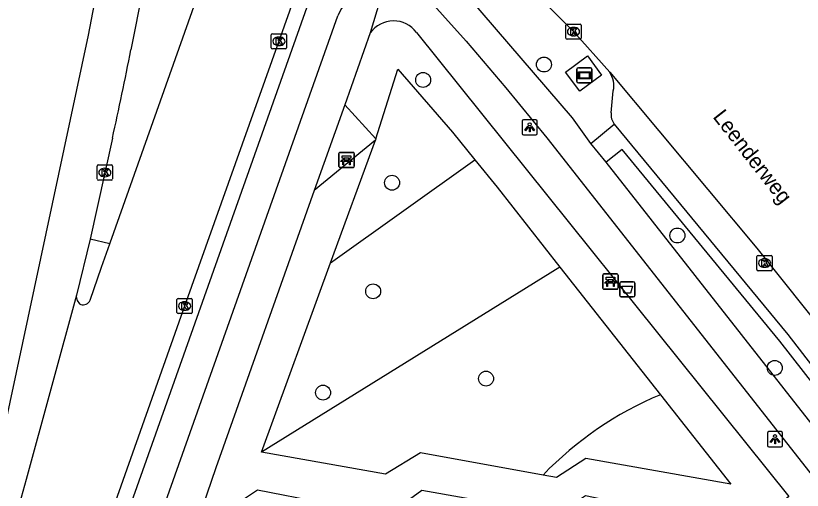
# Model space of a CAD drawing. Extents: x 161845 to 162341, y 381620 to 382158.
# Drawn here: x 161927.1 to 161978.7, y 382079 to 382110.2 of the extents above; entities that cross this region are included whole.
import ezdxf

# ---------------------------------------------------------------- set-up
doc = ezdxf.new("R2010")
doc.units = 0
for name, color, linetype in [('IMGEO_Afvalbak', 7, 'Continuous'), ('IMGEO_Bank', 7, 'Continuous'), ('IMGEO_Boom', 7, 'Continuous'), ('IMGEO_Fietspad_gesloten', 7, 'Continuous'), ('IMGEO_Groenvoorziening', 7, 'Continuous'), ('IMGEO_Kolk', 7, 'Continuous'), ('IMGEO_Lichtpunt', 7, 'Continuous'), ('IMGEO_Openbare_ruimte_label', 7, 'Continuous'), ('IMGEO_OVBaan_gesloten', 7, 'Continuous'), ('IMGEO_Parkeervlak_open', 7, 'Continuous'), ('IMGEO_Reclamebord', 7, 'Continuous'), ('IMGEO_Rijbaan_lokaal_gesloten', 7, 'Continuous'), ('IMGEO_Verkeerseiland_groen', 7, 'Continuous'), ('IMGEO_Voetpad_open', 7, 'Continuous')]:
    doc.layers.add(name, color=color, linetype=linetype)

msp = doc.modelspace()

# ---------------------------------------------------------------- linework, layer by layer
at = {"layer": 'IMGEO_Afvalbak'}
for p, q in [((161966.754, 382091.842), (161966.754, 382092.642)), ((161966.754, 382092.642), (161966.754, 382091.842)), ((161966.854, 382092.742), (161967.644, 382092.742)), ((161967.644, 382092.742), (161966.854, 382092.742)), ((161967.744, 382092.642), (161967.744, 382091.842)), ((161967.744, 382091.842), (161967.744, 382092.642)), ((161967.644, 382091.742), (161966.854, 382091.742)), ((161966.854, 382091.742), (161967.644, 382091.742))]:
    msp.add_line(p, q, dxfattribs=at)
msp.add_lwpolyline([(161966.897, 382092.456), (161967.601, 382092.456), (161967.452, 382091.986), (161967.046, 382091.986), (161966.897, 382092.456)], dxfattribs=at)
for centre, start, end in [((161966.854, 382092.642), 90, 180), ((161966.854, 382092.642), 90, 180), ((161967.644, 382092.642), 0, 90), ((161967.644, 382092.642), 360, 90), ((161966.854, 382091.842), 180, 270), ((161966.854, 382091.842), 180, 270), ((161967.644, 382091.842), 270, 0), ((161967.644, 382091.842), 270, 0)]:
    msp.add_arc(centre, 0.1, start, end, dxfattribs=at)
at = {"layer": 'IMGEO_Bank'}
for p, q in [((161948.316, 382100.316), (161948.316, 382101.157)), ((161948.316, 382101.157), (161948.316, 382100.316)), ((161948.391, 382101.241), (161949.232, 382101.241)), ((161949.232, 382101.241), (161948.391, 382101.241)), ((161949.316, 382101.166), (161949.316, 382100.325)), ((161949.316, 382100.325), (161949.316, 382101.166)), ((161949.013, 382100.639), (161948.62, 382100.639)), ((161948.625, 382100.747), (161948.625, 382100.853)), ((161948.669, 382100.853), (161948.669, 382100.747)), ((161948.957, 382100.859), (161948.675, 382100.859)), ((161948.675, 382100.741), (161948.957, 382100.741)), ((161948.963, 382100.747), (161948.963, 382100.853)), ((161949.007, 382100.853), (161949.007, 382100.747)), ((161949.241, 382100.241), (161948.4, 382100.241)), ((161948.4, 382100.241), (161949.241, 382100.241)), ((161965.645, 382092.331), (161965.645, 382093.172)), ((161965.645, 382093.172), (161965.645, 382092.331)), ((161965.72, 382093.256), (161966.561, 382093.256)), ((161966.561, 382093.256), (161965.72, 382093.256)), ((161966.286, 382092.874), (161966.004, 382092.874)), ((161966.645, 382093.181), (161966.645, 382092.34)), ((161966.645, 382092.34), (161966.645, 382093.181)), ((161966.342, 382092.654), (161965.949, 382092.654)), ((161965.954, 382092.762), (161965.954, 382092.868)), ((161965.998, 382092.868), (161965.998, 382092.762)), ((161966.004, 382092.756), (161966.286, 382092.756)), ((161966.292, 382092.762), (161966.292, 382092.868)), ((161966.336, 382092.868), (161966.336, 382092.762)), ((161966.57, 382092.256), (161965.729, 382092.256)), ((161965.729, 382092.256), (161966.57, 382092.256))]:
    msp.add_line(p, q, dxfattribs=at)
for points in [[(161948.563, 382100.639), (161948.421, 382100.639), (161948.533, 382100.741), (161948.619, 382100.741)], [(161948.619, 382100.859), (161948.533, 382100.859), (161948.533, 382101.02), (161949.096, 382101.02), (161949.096, 382100.859), (161949.013, 382100.859)], [(161948.613, 382100.632), (161948.613, 382100.425), (161948.57, 382100.425), (161948.57, 382100.632)], [(161949.013, 382100.741), (161949.096, 382100.741), (161949.208, 382100.639), (161949.069, 382100.639)], [(161949.063, 382100.632), (161949.063, 382100.425), (161949.019, 382100.425), (161949.019, 382100.632)], [(161965.948, 382092.874), (161965.862, 382092.874), (161965.862, 382093.035), (161966.425, 382093.035), (161966.425, 382092.874), (161966.342, 382092.874)], [(161965.892, 382092.654), (161965.75, 382092.654), (161965.862, 382092.756), (161965.948, 382092.756)], [(161965.942, 382092.647), (161965.942, 382092.44), (161965.899, 382092.44), (161965.899, 382092.647)], [(161966.342, 382092.756), (161966.425, 382092.756), (161966.537, 382092.654), (161966.398, 382092.654)], [(161966.392, 382092.647), (161966.392, 382092.44), (161966.348, 382092.44), (161966.348, 382092.647)]]:
    msp.add_lwpolyline(points, dxfattribs=at)
for centre, radius, start, end in [((161948.394, 382101.163), 0.0779, 92.4484, 184.2845), ((161948.394, 382101.163), 0.0779, 92.4484, 184.2845), ((161949.238, 382101.163), 0.0779, 2.4484, 94.2845), ((161949.238, 382101.163), 0.0779, 2.4484, 94.2845), ((161948.563, 382100.632), 0.00671, 2.8957, 87.1043), ((161948.62, 382100.632), 0.00671, 92.8957, 177.1043), ((161948.618, 382100.852), 0.00671, 2.8957, 87.1043), ((161948.618, 382100.748), 0.00671, 272.8957, 357.1043), ((161948.675, 382100.852), 0.00671, 92.8957, 177.1043), ((161948.675, 382100.748), 0.00671, 182.8957, 267.1043), ((161948.957, 382100.852), 0.00671, 2.8957, 87.1043), ((161948.957, 382100.748), 0.00671, 272.8957, 357.1043), ((161949.014, 382100.852), 0.00671, 92.8957, 177.1043), ((161949.014, 382100.748), 0.00671, 182.8957, 267.1043), ((161949.012, 382100.632), 0.00671, 2.8957, 87.1043), ((161949.069, 382100.632), 0.00671, 92.8957, 177.1043), ((161948.394, 382100.319), 0.0779, 182.4484, 274.2845), ((161948.394, 382100.319), 0.0779, 182.4484, 274.2845), ((161949.238, 382100.319), 0.0779, 272.4484, 4.2845), ((161949.238, 382100.319), 0.0779, 272.4484, 4.2845), ((161965.723, 382093.178), 0.0779, 92.4484, 184.2845), ((161965.723, 382093.178), 0.0779, 92.4484, 184.2845), ((161965.947, 382092.867), 0.00671, 2.8957, 87.1043), ((161966.004, 382092.867), 0.00671, 92.8957, 177.1043), ((161966.286, 382092.867), 0.00671, 2.8957, 87.1043), ((161966.343, 382092.867), 0.00671, 92.8957, 177.1043), ((161966.567, 382093.178), 0.0779, 2.4484, 94.2845), ((161966.567, 382093.178), 0.0779, 2.4484, 94.2845), ((161965.892, 382092.647), 0.00671, 2.8957, 87.1043), ((161965.949, 382092.647), 0.00671, 92.8957, 177.1043), ((161965.947, 382092.763), 0.00671, 272.8957, 357.1043), ((161966.004, 382092.763), 0.00671, 182.8957, 267.1043), ((161966.286, 382092.763), 0.00671, 272.8957, 357.1043), ((161966.343, 382092.763), 0.00671, 182.8957, 267.1043), ((161966.341, 382092.647), 0.00671, 2.8957, 87.1043), ((161966.398, 382092.647), 0.00671, 92.8957, 177.1043), ((161965.723, 382092.334), 0.0779, 182.4484, 274.2845), ((161965.723, 382092.334), 0.0779, 182.4484, 274.2845), ((161966.567, 382092.334), 0.0779, 272.4484, 4.2845), ((161966.567, 382092.334), 0.0779, 272.4484, 4.2845)]:
    msp.add_arc(centre, radius, start, end, dxfattribs=at)
at = {"layer": 'IMGEO_Boom'}
for centre in [(161961.778, 382107.01), (161953.848, 382106), (161951.807, 382099.243), (161970.541, 382095.78), (161950.565, 382092.113), (161976.936, 382087.084), (161957.978, 382086.381), (161947.278, 382085.46)]:
    msp.add_circle(centre, 0.489, dxfattribs=at)
at = {"layer": 'IMGEO_Fietspad_gesloten'}
for points in [[(161929.692, 382064.104), (161946.705, 382112.189)], [(161930.559, 382060.292), (161948.248, 382110.215)]]:
    msp.add_lwpolyline(points, dxfattribs=at)
msp.add_arc((161951.718, 382108.75), 3.767, 94.7236, 157.1131, dxfattribs=at)
at = {"layer": 'IMGEO_Groenvoorziening'}
for points in [[(161950.738, 382102.124), (161952.187, 382106.704), (161955.767, 382102.569), (161957.25, 382100.745)], [(161947.765, 382093.975), (161950.71, 382102.036)], [(161947.765, 382093.975), (161957.25, 382100.745)], [(161957.25, 382100.745), (161958.711, 382098.948), (161962.832, 382093.707)], [(161943.229, 382081.558), (161947.765, 382093.975)], [(161962.832, 382093.707), (161943.229, 382081.558)], [(161962.832, 382093.707), (161969.423, 382085.325)], [(161969.423, 382085.325), (161974.048, 382079.443), (161964.538, 382081.14), (161962.599, 382079.888), (161961.719, 382080.048)], [(161961.719, 382080.048), (161953.667, 382081.508), (161951.366, 382080.101), (161943.229, 382081.558)]]:
    msp.add_lwpolyline(points, dxfattribs=at)
msp.add_arc((161978.375, 382063.993), 23.134, 112.7665, 136.0534, dxfattribs=at)
at = {"layer": 'IMGEO_Kolk'}
for p, q in [((161963.221, 382108.744), (161963.221, 382109.596)), ((161963.296, 382109.67), (161964.148, 382109.67)), ((161963.709, 382109.45), (161963.734, 382109.45)), ((161964.222, 382109.596), (161964.222, 382108.744)), ((161943.879, 382108.109), (161943.879, 382108.961)), ((161943.954, 382109.035), (161944.806, 382109.035)), ((161944.88, 382108.961), (161944.88, 382108.109)), ((161963.732, 382108.89), (161963.707, 382108.89)), ((161944.367, 382108.815), (161944.392, 382108.815)), ((161964.148, 382108.67), (161963.296, 382108.67)), ((161944.806, 382108.035), (161943.954, 382108.035)), ((161944.39, 382108.255), (161944.365, 382108.255)), ((161932.448, 382099.491), (161932.448, 382100.343)), ((161932.523, 382100.417), (161933.375, 382100.417)), ((161932.936, 382100.197), (161932.961, 382100.197)), ((161933.449, 382100.343), (161933.449, 382099.491)), ((161932.959, 382099.637), (161932.934, 382099.637)), ((161933.375, 382099.417), (161932.523, 382099.417)), ((161975.841, 382094.469), (161976.693, 382094.469)), ((161975.766, 382093.543), (161975.766, 382094.395)), ((161976.254, 382094.249), (161976.279, 382094.249)), ((161976.767, 382094.395), (161976.767, 382093.543)), ((161976.693, 382093.469), (161975.841, 382093.469)), ((161976.277, 382093.689), (161976.252, 382093.689)), ((161937.686, 382090.721), (161937.686, 382091.573)), ((161937.761, 382091.647), (161938.613, 382091.647)), ((161938.174, 382091.427), (161938.199, 382091.427)), ((161938.687, 382091.573), (161938.687, 382090.721)), ((161938.197, 382090.867), (161938.172, 382090.867)), ((161938.613, 382090.647), (161937.761, 382090.647))]:
    msp.add_line(p, q, dxfattribs=at)
for points in [[(161963.221, 382108.744), (161963.221, 382109.596)], [(161963.296, 382109.67), (161964.148, 382109.67)], [(161964.222, 382109.596), (161964.222, 382108.744)], [(161943.879, 382108.109), (161943.879, 382108.961)], [(161943.954, 382109.035), (161944.806, 382109.035)], [(161944.88, 382108.961), (161944.88, 382108.109)], [(161963.542, 382109.37), (161963.665, 382109.37), (161963.665, 382109.219), (161963.795, 382109.37), (161963.959, 382109.37), (161963.813, 382109.219), (161963.966, 382108.97), (161963.814, 382108.97), (161963.729, 382109.134), (161963.665, 382109.067), (161963.665, 382108.97), (161963.542, 382108.97), (161963.542, 382109.37)], [(161944.2, 382108.735), (161944.323, 382108.735), (161944.323, 382108.584), (161944.453, 382108.735), (161944.617, 382108.735), (161944.471, 382108.584), (161944.624, 382108.335), (161944.472, 382108.335), (161944.387, 382108.499), (161944.323, 382108.432), (161944.323, 382108.335), (161944.2, 382108.335), (161944.2, 382108.735)], [(161964.148, 382108.67), (161963.296, 382108.67)], [(161944.806, 382108.035), (161943.954, 382108.035)], [(161932.448, 382099.491), (161932.448, 382100.343)], [(161932.523, 382100.417), (161933.375, 382100.417)], [(161932.769, 382100.117), (161932.892, 382100.117), (161932.892, 382099.966), (161933.022, 382100.117), (161933.186, 382100.117), (161933.04, 382099.966), (161933.193, 382099.717), (161933.041, 382099.717), (161932.956, 382099.881), (161932.892, 382099.814), (161932.892, 382099.717), (161932.769, 382099.717), (161932.769, 382100.117)], [(161933.449, 382100.343), (161933.449, 382099.491)], [(161933.375, 382099.417), (161932.523, 382099.417)], [(161975.841, 382094.469), (161976.693, 382094.469)], [(161975.766, 382093.543), (161975.766, 382094.395)], [(161976.087, 382094.169), (161976.21, 382094.169), (161976.21, 382094.018), (161976.34, 382094.169), (161976.504, 382094.169), (161976.358, 382094.018), (161976.511, 382093.769), (161976.359, 382093.769), (161976.274, 382093.933), (161976.21, 382093.866), (161976.21, 382093.769), (161976.087, 382093.769), (161976.087, 382094.169)], [(161976.767, 382094.395), (161976.767, 382093.543)], [(161976.693, 382093.469), (161975.841, 382093.469)], [(161937.686, 382090.721), (161937.686, 382091.573)], [(161937.761, 382091.647), (161938.613, 382091.647)], [(161938.007, 382091.347), (161938.13, 382091.347), (161938.13, 382091.196), (161938.26, 382091.347), (161938.424, 382091.347), (161938.278, 382091.196), (161938.431, 382090.947), (161938.279, 382090.947), (161938.194, 382091.111), (161938.13, 382091.044), (161938.13, 382090.947), (161938.007, 382090.947), (161938.007, 382091.347)], [(161938.687, 382091.573), (161938.687, 382090.721)], [(161938.613, 382090.647), (161937.761, 382090.647)]]:
    msp.add_lwpolyline(points, dxfattribs=at)
for centre, start, end in [((161963.298, 382109.594), 91.552, 178.448), ((161963.298, 382109.594), 91.552, 178.448), ((161964.146, 382109.594), 1.552, 88.448), ((161964.146, 382109.594), 1.552, 88.448), ((161943.956, 382108.959), 91.552, 178.448), ((161943.956, 382108.959), 91.552, 178.448), ((161944.804, 382108.959), 1.552, 88.448), ((161944.804, 382108.959), 1.552, 88.448), ((161963.298, 382108.746), 181.552, 268.448), ((161963.298, 382108.746), 181.552, 268.448), ((161964.146, 382108.746), 271.552, 358.448), ((161964.146, 382108.746), 271.552, 358.448), ((161943.956, 382108.111), 181.552, 268.448), ((161943.956, 382108.111), 181.552, 268.448), ((161944.804, 382108.111), 271.552, 358.448), ((161944.804, 382108.111), 271.552, 358.448), ((161932.525, 382100.341), 91.552, 178.448), ((161932.525, 382100.341), 91.552, 178.448), ((161933.373, 382100.341), 1.552, 88.448), ((161933.373, 382100.341), 1.552, 88.448), ((161932.525, 382099.493), 181.552, 268.448), ((161932.525, 382099.493), 181.552, 268.448), ((161933.373, 382099.493), 271.552, 358.448), ((161933.373, 382099.493), 271.552, 358.448), ((161975.843, 382094.393), 91.552, 178.448), ((161975.843, 382094.393), 91.552, 178.448), ((161976.691, 382094.393), 1.552, 88.448), ((161976.691, 382094.393), 1.552, 88.448), ((161975.843, 382093.545), 181.552, 268.448), ((161975.843, 382093.545), 181.552, 268.448), ((161976.691, 382093.545), 271.552, 358.448), ((161976.691, 382093.545), 271.552, 358.448), ((161937.763, 382091.571), 91.552, 178.448), ((161937.763, 382091.571), 91.552, 178.448), ((161938.611, 382091.571), 1.552, 88.448), ((161938.611, 382091.571), 1.552, 88.448), ((161937.763, 382090.723), 181.552, 268.448), ((161937.763, 382090.723), 181.552, 268.448), ((161938.611, 382090.723), 271.552, 358.448), ((161938.611, 382090.723), 271.552, 358.448)]:
    msp.add_arc(centre, 0.0765, start, end, dxfattribs=at)
for centre, major_axis, ratio, start_param, end_param in [((161963.708, 382109.17), (-0.387, 0.002), 0.722429, 4.712389, 7.853982), ((161963.733, 382109.17), (-0.39, 0.002), 0.717154, 1.570796, 4.712389), ((161944.366, 382108.535), (-0.387, 0.002), 0.722429, 4.712389, 7.853982), ((161944.391, 382108.535), (-0.39, 0.002), 0.717154, 1.570796, 4.712389), ((161932.935, 382099.917), (-0.387, 0.002), 0.722429, 4.712389, 7.853982), ((161932.96, 382099.917), (-0.39, 0.002), 0.717154, 1.570796, 4.712389), ((161976.253, 382093.969), (-0.387, 0.002), 0.722429, 4.712389, 7.853982), ((161976.278, 382093.969), (-0.39, 0.002), 0.717154, 1.570796, 4.712389), ((161938.173, 382091.147), (-0.387, 0.002), 0.722429, 4.712389, 7.853982), ((161938.198, 382091.147), (-0.39, 0.002), 0.717154, 1.570796, 4.712389)]:
    msp.add_ellipse(centre, major_axis=major_axis, ratio=ratio, start_param=start_param, end_param=end_param, dxfattribs=at)
at = {"layer": 'IMGEO_Lichtpunt'}
for p, q in [((161960.347, 382103.288), (161960.347, 382102.481)), ((161960.347, 382103.288), (161960.347, 382102.481)), ((161961.249, 382103.383), (161960.441, 382103.383)), ((161961.249, 382103.383), (161960.441, 382103.383)), ((161961.343, 382102.481), (161961.343, 382103.288)), ((161961.343, 382102.481), (161961.343, 382103.288)), ((161960.441, 382102.387), (161961.249, 382102.387)), ((161960.441, 382102.387), (161961.249, 382102.387)), ((161976.454, 382082.803), (161976.454, 382081.996)), ((161976.454, 382082.803), (161976.454, 382081.996)), ((161977.356, 382082.898), (161976.548, 382082.898)), ((161977.356, 382082.898), (161976.548, 382082.898)), ((161977.45, 382081.996), (161977.45, 382082.803)), ((161977.45, 382081.996), (161977.45, 382082.803)), ((161976.548, 382081.902), (161977.356, 382081.902)), ((161976.548, 382081.902), (161977.356, 382081.902))]:
    msp.add_line(p, q, dxfattribs=at)
for points in [[(161960.721, 382102.952), (161960.76, 382102.924), (161960.572, 382102.662), (161960.534, 382102.689), (161960.721, 382102.952)], [(161960.823, 382102.904), (161960.87, 382102.904), (161960.87, 382102.582), (161960.823, 382102.582), (161960.823, 382102.904)], [(161960.933, 382102.924), (161960.971, 382102.951), (161961.158, 382102.689), (161961.119, 382102.661), (161960.933, 382102.924)], [(161976.828, 382082.467), (161976.867, 382082.439), (161976.679, 382082.177), (161976.641, 382082.204), (161976.828, 382082.467)], [(161976.93, 382082.419), (161976.977, 382082.419), (161976.977, 382082.097), (161976.93, 382082.097), (161976.93, 382082.419)], [(161977.04, 382082.439), (161977.078, 382082.466), (161977.265, 382082.204), (161977.226, 382082.176), (161977.04, 382082.439)]]:
    msp.add_lwpolyline(points, dxfattribs=at)
for centre in [(161960.846, 382103.086), (161976.953, 382082.601)]:
    msp.add_circle(centre, 0.0994, dxfattribs=at)
for centre, start, end in [((161960.441, 382103.288), 90, 180), ((161960.441, 382103.288), 90, 180), ((161961.249, 382103.288), 0, 90), ((161961.249, 382103.288), 0, 90), ((161960.441, 382102.481), 180, 270), ((161960.441, 382102.481), 180, 270), ((161961.249, 382102.481), 270, 0), ((161961.249, 382102.481), 270, 360), ((161976.548, 382082.803), 90, 180), ((161976.548, 382082.803), 90, 180), ((161977.356, 382082.803), 0, 90), ((161977.356, 382082.803), 0, 90), ((161976.548, 382081.996), 180, 270), ((161976.548, 382081.996), 180, 270), ((161977.356, 382081.996), 270, 0), ((161977.356, 382081.996), 270, 360)]:
    msp.add_arc(centre, 0.0946, start, end, dxfattribs=at)
at = {"layer": 'IMGEO_OVBaan_gesloten'}
for points in [[(161915.767, 382027.092), (161920.812, 382054.098), (161923.657, 382069.694), (161925.944, 382081.248), (161931.886, 382108.929), (161933.831, 382119.131), (161934.302, 382121.796), (161934.443, 382123.117)], [(161937.124, 382120.558), (161936.261, 382116.022), (161934.665, 382107.97)], [(161933.446, 382102.165), (161931.986, 382095.547)], [(161931.986, 382095.547), (161931.078, 382091.863)], [(161931.078, 382091.863), (161927.783, 382079.758)]]:
    msp.add_lwpolyline(points, dxfattribs=at)
for centre, radius, start, end in [((161596.403, 382175.972), 345.03, 347.64818, 348.6332), ((162474.126, 381930.5), 566.364, 164.71995, 168.67512)]:
    msp.add_arc(centre, radius, start, end, dxfattribs=at)
at = {"layer": 'IMGEO_Parkeervlak_open'}
msp.add_lwpolyline([(161966.197, 382103.843), (161966.334, 382105.277)], dxfattribs=at)
for centre, radius, start, end in [((161964.767, 382105.606), 1.601, 348.1282, 33.8412), ((161967.165, 382103.708), 0.977, 172.0517, 218.4062)]:
    msp.add_arc(centre, radius, start, end, dxfattribs=at)
at = {"layer": 'IMGEO_Reclamebord'}
for p, q in [((161963.938, 382105.903), (161963.938, 382106.703)), ((161963.938, 382106.703), (161963.938, 382105.903)), ((161964.038, 382106.803), (161964.828, 382106.803)), ((161964.828, 382106.803), (161964.038, 382106.803)), ((161964.928, 382106.703), (161964.928, 382105.903)), ((161964.928, 382105.903), (161964.928, 382106.703)), ((161964.828, 382105.803), (161964.038, 382105.803)), ((161964.038, 382105.803), (161964.828, 382105.803))]:
    msp.add_line(p, q, dxfattribs=at)
for points in [[(161964.039, 382106.535), (161964.827, 382106.535), (161964.827, 382106.071), (161964.039, 382106.071), (161964.039, 382106.535)], [(161964.104, 382106.47), (161964.104, 382106.136), (161964.762, 382106.136), (161964.762, 382106.47), (161964.104, 382106.47)]]:
    msp.add_lwpolyline(points, dxfattribs=at)
for centre, start, end in [((161964.038, 382106.703), 90, 180), ((161964.038, 382106.703), 90, 180), ((161964.828, 382106.703), 0, 90), ((161964.828, 382106.703), 360, 90), ((161964.038, 382105.903), 180, 270), ((161964.038, 382105.903), 180, 270), ((161964.828, 382105.903), 270, 0), ((161964.828, 382105.903), 270, 0)]:
    msp.add_arc(centre, 0.1, start, end, dxfattribs=at)
at = {"layer": 'IMGEO_Rijbaan_lokaal_gesloten'}
for points in [[(161954.56, 382117.519), (161959.149, 382113.492), (161962.131, 382110.773), (161963.722, 382109.17), (161966.097, 382106.498)], [(161933.277, 382095.234), (161933.303, 382095.307), (161939.668, 382113.293)], [(161945.765, 382112.51), (161944.379, 382108.536), (161938.187, 382091.148), (161931.341, 382071.839)], [(161966.097, 382106.498), (161975.767, 382094.947), (161982.236, 382086.82), (161986.686, 382080.916)], [(161931.986, 382091.523), (161932.734, 382093.698), (161933.277, 382095.234)]]:
    msp.add_lwpolyline(points, dxfattribs=at)
for centre, radius, start, end in [((161931.689, 382091.777), 0.617, 172.0176, 238.8511), ((161931.512, 382091.76), 0.53, 254.4859, 333.4736)]:
    msp.add_arc(centre, radius, start, end, dxfattribs=at)
at = {"layer": 'IMGEO_Verkeerseiland_groen'}
msp.add_lwpolyline([(161964.634, 382107.576), (161965.569, 382106.316), (161964.132, 382105.25), (161963.197, 382106.51), (161964.634, 382107.576)], dxfattribs=at)
at = {"layer": 'IMGEO_Voetpad_open'}
for points in [[(161964.851, 382101.816), (161963.65, 382103.514), (161953.55, 382115.281)], [(161951.408, 382112.504), (161950.378, 382109.088)], [(161953.558, 382112.035), (161956.669, 382108.552), (161959.271, 382105.479), (161961.971, 382102.2), (161987.189, 382070.102)], [(161953.409, 382109.112), (161977.867, 382078.64), (161975.269, 382076.433), (161964.501, 382078.687), (161962.67, 382077.458), (161953.759, 382079.027), (161951.501, 382077.385), (161942.969, 382079.051), (161939.681, 382076.868), (161939.066, 382077.135)], [(161950.378, 382109.088), (161948.71, 382104.372)], [(161948.71, 382104.372), (161946.691, 382098.74)], [(161948.71, 382104.372), (161950.738, 382102.124)], [(161964.851, 382101.816), (161966.399, 382103.101)], [(161966.399, 382103.101), (161977.789, 382089.284), (161983.411, 382081.99)], [(161950.71, 382102.036), (161946.691, 382098.74)], [(161950.738, 382102.124), (161950.71, 382102.036)], [(161965.856, 382100.591), (161964.851, 382101.816)], [(161980.589, 382081.833), (161981.923, 382082.853), (161977.26, 382088.844), (161966.921, 382101.439), (161965.856, 382100.591)], [(161980.589, 382081.833), (161965.856, 382100.591)], [(161946.691, 382098.74), (161940.239, 382080.524), (161939.066, 382077.135)], [(161933.277, 382095.234), (161931.986, 382095.547)]]:
    msp.add_lwpolyline(points, dxfattribs=at)
msp.add_arc((161951.902, 382108.011), 1.867, 36.1649, 144.7425, dxfattribs=at)

# ---------------------------------------------------------------- texts
at = {"layer": 'IMGEO_Openbare_ruimte_label'}
msp.add_text('Leenderweg', height=1, rotation=308.0157, dxfattribs=at).set_placement((161972.828, 382103.562))

doc.saveas('drawing.dxf')
